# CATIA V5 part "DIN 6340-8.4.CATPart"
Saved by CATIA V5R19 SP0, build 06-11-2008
Definition: DIN 6340-8.4
Nomenclature: DIN 6340-8.4
Description: PART--DESC
Material "Steel": density 7860 kg/m3, Young's modulus 2e+11 Pa, Poisson ratio 0.266, thermal expansion 1.17e-05 1/K
Bounding box of the stored display mesh (mm): x 158 to 176, y -100.5 to -82.5, z 83 to 85.5
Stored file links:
  G:\UTB\Kombinované\Bakalářská práce\Catia\FORMA\DIN 6340-8.4.CATPart
  D:\Aplikace\CATIA\Nová složka\win_b64\startup\materials\Catalog.CATMaterial
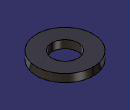
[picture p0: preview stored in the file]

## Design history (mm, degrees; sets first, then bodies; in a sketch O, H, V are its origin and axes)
Body1 "DIN 6340-8.4" (main body)
  Solid1: solid without history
